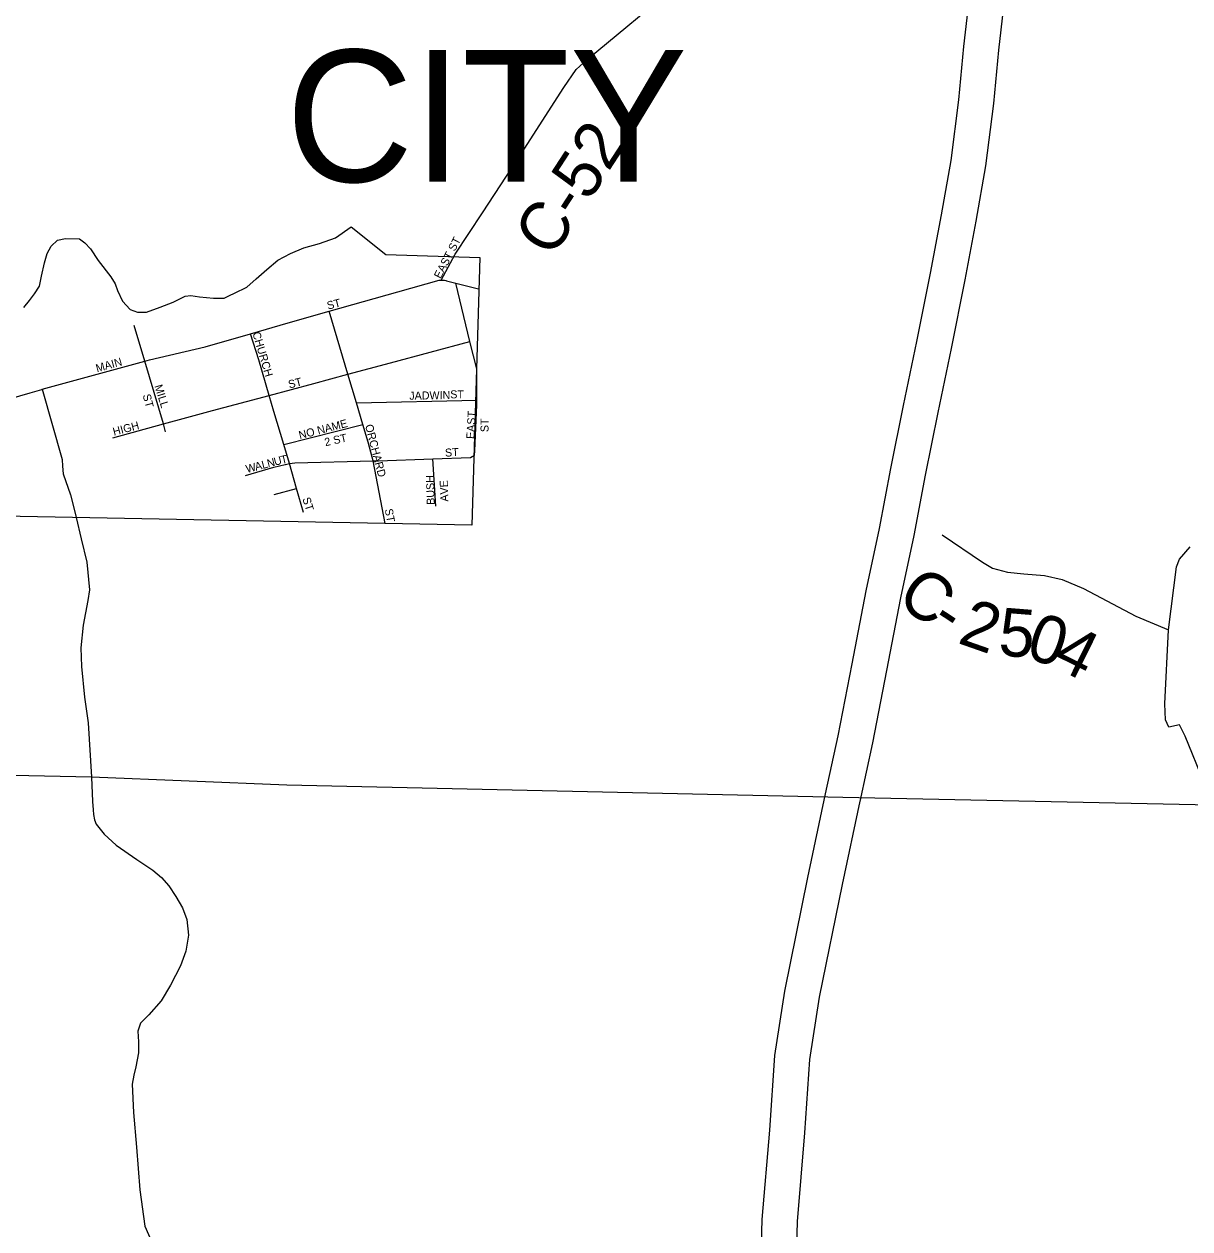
# Model space of a CAD drawing. Extents: x 0 to 34, y 0 to 22.
# Drawn here: x 26.145 to 27.522, y 17.734 to 19.156 of the extents above; entities that cross this region are included whole.
import ezdxf

# ---------------------------------------------------------------- set-up
doc = ezdxf.new("R2010")
doc.units = 0
for name, color, linetype in [('Default', 7, 'Continuous'), ('GM_X_City_Street', 7, 'Continuous'), ('GM_X_City_Street_Text', 7, 'Continuous'), ('GM_X_Corporation', 7, 'Continuous'), ('GM_X_County_Road_Text', 7, 'Continuous'), ('GM_X_State_Route', 7, 'Continuous'), ('GM_X_Township', 7, 'Continuous'), ('GM_X_Unincorporated_Text', 7, 'Continuous')]:
    doc.layers.add(name, color=color, linetype=linetype)

msp = doc.modelspace()

# ---------------------------------------------------------------- linework, layer by layer
at = {"layer": 'Default'}
for points in [[(26.6544, 18.8848), (26.6866, 18.9336), (26.7357, 19.0086), (26.7826, 19.0814), (26.7971, 19.1028), (26.8101, 19.1147), (26.9177, 19.2038), (26.9307, 19.2192), (26.9383, 19.2328), (26.9453, 19.2455), (26.9545, 19.2737), (26.9555, 19.2789)], [(27.2293, 18.5533), (27.2771, 18.5209), (27.2887, 18.514), (27.3067, 18.5092), (27.3259, 18.5075), (27.3504, 18.5053), (27.3711, 18.5005), (27.3962, 18.49), (27.4583, 18.4575), (27.4969, 18.4411)], [(27.5388, 18.2607), (27.5165, 18.3156), (27.5097, 18.3291), (27.4971, 18.3263), (27.4931, 18.335), (27.4925, 18.3539), (27.4969, 18.4411), (27.5061, 18.5156), (27.5096, 18.5246), (27.5222, 18.5392)]]:
    msp.add_lwpolyline(points, dxfattribs=at)
at = {"layer": 'GM_X_City_Street'}
for points in [[(26.6379, 18.854), (26.6544, 18.8848)], [(26.1669, 18.7253), (26.2879, 18.7585), (26.2935, 18.76), (26.3593, 18.7753), (26.4128, 18.7907), (26.4572, 18.8036), (26.5058, 18.8173), (26.5868, 18.8402), (26.6356, 18.854), (26.6379, 18.854), (26.6416, 18.854), (26.6435, 18.8535), (26.6442, 18.8533)], [(26.6442, 18.8533), (26.6551, 18.8505), (26.6818, 18.8437)], [(26.6773, 18.6475), (26.6777, 18.6524), (26.6798, 18.7068), (26.6799, 18.7125), (26.68, 18.7495), (26.672, 18.7799), (26.6717, 18.7814), (26.6551, 18.8505)], [(26.5563, 18.645), (26.5516, 18.6626), (26.5453, 18.6836), (26.5377, 18.7091), (26.5276, 18.7429), (26.5058, 18.8173)], [(26.3125, 18.6749), (26.3098, 18.6842), (26.2879, 18.7585), (26.2755, 18.8004)], [(26.4753, 18.5796), (26.4672, 18.6082), (26.4589, 18.6377), (26.4521, 18.6599), (26.4401, 18.6991), (26.4346, 18.7179), (26.4224, 18.7598), (26.4128, 18.7907)], [(26.3677, 18.7), (26.368, 18.7001), (26.4346, 18.7179), (26.4876, 18.7322), (26.5276, 18.7429), (26.5779, 18.7564), (26.6717, 18.7814)], [(26.5377, 18.7091), (26.6799, 18.7125)], [(26.2503, 18.6677), (26.3098, 18.6842), (26.3376, 18.692), (26.3677, 18.7)], [(26.4521, 18.6599), (26.5453, 18.6836)], [(26.4539, 18.6365), (26.4589, 18.6377), (26.465, 18.6383), (26.5574, 18.6407), (26.5638, 18.6409), (26.6282, 18.643), (26.6723, 18.6445), (26.6773, 18.6475)], [(26.4069, 18.6235), (26.4401, 18.6333), (26.4535, 18.6365), (26.4539, 18.6365)], [(26.5716, 18.5667), (26.5574, 18.6407), (26.5563, 18.6449), (26.5563, 18.645)], [(26.6314, 18.5872), (26.6282, 18.643)], [(26.4405, 18.6008), (26.4672, 18.6082)]]:
    msp.add_lwpolyline(points, dxfattribs=at)
at = {"layer": 'GM_X_Corporation'}
msp.add_lwpolyline([(26.1452, 18.8218), (26.1516, 18.83), (26.1575, 18.8378), (26.1634, 18.847), (26.166, 18.8588), (26.1693, 18.8745), (26.1726, 18.8856), (26.1772, 18.8941), (26.185, 18.9013), (26.1942, 18.9033), (26.2106, 18.9026), (26.2171, 18.898), (26.2236, 18.8908), (26.2328, 18.8771), (26.2479, 18.8581), (26.2531, 18.8496), (26.2557, 18.8417), (26.2616, 18.8293), (26.2708, 18.8195), (26.2793, 18.8162), (26.2898, 18.8162), (26.3061, 18.8221), (26.3212, 18.828), (26.3356, 18.8352), (26.3422, 18.8358), (26.3526, 18.8345), (26.369, 18.8326), (26.3815, 18.8326), (26.388, 18.8358), (26.3939, 18.8385), (26.4083, 18.8457), (26.4194, 18.8555), (26.4319, 18.8666), (26.445, 18.8777), (26.46, 18.8856), (26.4757, 18.8921), (26.4941, 18.8974), (26.5131, 18.9039), (26.5314, 18.917), (26.5727, 18.8844), (26.6837, 18.8806), (26.6742, 18.5648), (26.0789, 18.5761)], dxfattribs=at)
at = {"layer": 'GM_X_State_Route'}
for points in [[(27.0918, 18.2475), (27.1066, 18.3161), (27.1233, 18.4012), (27.1397, 18.4872), (27.1554, 18.5608), (27.1689, 18.6316), (27.1839, 18.7062), (27.1996, 18.7817), (27.2156, 18.8624), (27.2287, 18.9312), (27.2399, 18.9951), (27.249, 19.067), (27.2551, 19.1298), (27.2622, 19.1912), (27.2652, 19.2497), (27.2696, 19.2987), (27.2708, 19.3576), (27.2709, 19.4673), (27.2695, 19.511), (27.2681, 19.5495), (27.2651, 19.6066), (27.2603, 19.6678)], [(27.1325, 18.2387), (27.1474, 18.3077), (27.1641, 18.3933), (27.1805, 18.4789), (27.1962, 18.5526), (27.2097, 18.6237), (27.2247, 18.6979), (27.2404, 18.7734), (27.2565, 18.8544), (27.2696, 18.9237), (27.2811, 18.9889), (27.2904, 19.0624), (27.2965, 19.1254), (27.3036, 19.1877), (27.3067, 19.2467), (27.3112, 19.2964), (27.3124, 19.3572), (27.3125, 19.4679), (27.3111, 19.5124), (27.3096, 19.5514), (27.3066, 19.6093), (27.3017, 19.671)], [(26.0321, 18.6873), (26.1281, 18.7141), (26.1526, 18.721), (26.1662, 18.7251)], [(26.1662, 18.7251), (26.1669, 18.7253), (26.1903, 18.6424), (26.1906, 18.6345), (26.1915, 18.6255), (26.2, 18.6004), (26.2048, 18.5822)], [(26.2048, 18.5822), (26.207, 18.5738), (26.2129, 18.5487), (26.2196, 18.5212), (26.2224, 18.4884), (26.2207, 18.476), (26.2151, 18.4466), (26.2122, 18.4201), (26.213, 18.3978), (26.2168, 18.3619), (26.2211, 18.3316), (26.2248, 18.2671)], [(26.2248, 18.2671), (26.2263, 18.2384), (26.2269, 18.2285), (26.2275, 18.223), (26.2286, 18.2169), (26.2305, 18.2117), (26.24, 18.1999), (26.2541, 18.1868), (26.2785, 18.17), (26.2972, 18.1574), (26.3077, 18.149), (26.3163, 18.1389), (26.3247, 18.1262), (26.3323, 18.1131), (26.3374, 18.0992), (26.3395, 18.0807), (26.3365, 18.0617), (26.3302, 18.0445), (26.3183, 18.0219), (26.3073, 18.0034), (26.2928, 17.9868), (26.283, 17.9767), (26.2797, 17.9675), (26.2806, 17.9547), (26.2803, 17.9419), (26.2773, 17.9253), (26.275, 17.9155), (26.2729, 17.9048), (26.2747, 17.8712), (26.2779, 17.8306), (26.2821, 17.7801), (26.2879, 17.7372), (26.3039, 17.7007)], [(26.5826, 16.084), (26.839, 16.7847), (26.9392, 17.0672), (26.9517, 17.1025), (26.9691, 17.1529), (26.9833, 17.2094), (26.9966, 17.287), (27.0052, 17.3586), (27.008, 17.4687), (27.0141, 17.6436), (27.0171, 17.7452), (27.0258, 17.8505), (27.0317, 17.9388), (27.0437, 18.0148), (27.0708, 18.149), (27.0918, 18.2474)], [(26.6216, 16.0697), (26.8781, 16.7706), (26.9784, 17.0533), (26.9909, 17.0888), (27.009, 17.141), (27.024, 17.2008), (27.0378, 17.281), (27.0467, 17.3556), (27.0496, 17.4674), (27.0557, 17.6423), (27.0587, 17.7428), (27.0673, 17.8474), (27.0731, 17.9341), (27.0846, 18.0075), (27.1116, 18.1405), (27.1325, 18.2388)]]:
    msp.add_lwpolyline(points, dxfattribs=at)
at = {"layer": 'GM_X_Township'}
for p, q in [((26.2248, 18.2671), (25.791, 18.2762)), ((26.4556, 18.2579), (26.2248, 18.2671)), ((27.1122, 18.2431), (26.4556, 18.2579)), ((27.5471, 18.2342), (27.1122, 18.2431))]:
    msp.add_line(p, q, dxfattribs=at)

# ---------------------------------------------------------------- texts
at = {"layer": 'GM_X_City_Street_Text'}
for s, rotation, p in [('EAST ST', 62.4858, (26.6371, 18.855)), ('ST', 14.0362, (26.5043, 18.8192)), ('CHURCH', 286.6083, (26.4148, 18.7915)), ('MAIN', 15.5247, (26.2315, 18.7452)), ('ST', 14.0362, (26.4586, 18.7261)), ('ST', 284.9378, (26.2853, 18.7182)), ('MILL', 287.3515, (26.2992, 18.7291)), ('JADWIN', 1.0803, (26.6003, 18.7128)), ('ST', 0, (26.6486, 18.7145)), ('NO NAME', 14.4709, (26.471, 18.6662)), ('EAST', 86.7313, (26.6769, 18.6663)), ('ST', 90, (26.6938, 18.6746)), ('HIGH', 14.8275, (26.2515, 18.6703)), ('ORCHARD', 284.4461, (26.5479, 18.6825)), ('2 ST', 12.5258, (26.5012, 18.6579)), ('T', 12.4192, (26.4496, 18.637)), ('ST', 3.5746, (26.6427, 18.6455)), ('W', 14.6969, (26.4086, 18.6263)), ('A', 14.6829, (26.4191, 18.629)), ('L', 14.6965, (26.4272, 18.6311)), ('N', 14.6935, (26.4336, 18.6328)), ('U', 14.6935, (26.4416, 18.6349)), ('BUSH', 91.5474, (26.6303, 18.5889)), ('AVE', 91.9739, (26.6464, 18.5927)), ('ST', 287.3568, (26.4739, 18.5961)), ('ST', 280.6267, (26.5712, 18.5834))]:
    msp.add_text(s, height=0.00945, rotation=rotation, dxfattribs=at).set_placement(p)
at = {"layer": 'GM_X_County_Road_Text'}
for s, rotation, p in [('C-52', 56.9761, (26.7686, 18.8787)), ('C', 324.6048, (27.1735, 18.4738)), ('-', 326.6535, (27.2133, 18.4456)), ('2', 340.7081, (27.2463, 18.4261)), ('5', 355.429, (27.2948, 18.4112)), ('0', 341.895, (27.3261, 18.4091)), ('4', 333.6142, (27.3573, 18.3991))]:
    msp.add_text(s, height=0.0567, rotation=rotation, dxfattribs=at).set_placement(p)
at = {"layer": 'GM_X_Unincorporated_Text'}
msp.add_text('CITY', height=0.15568, rotation=0, dxfattribs=at).set_placement((26.4545, 18.9701))

doc.saveas('drawing.dxf')
